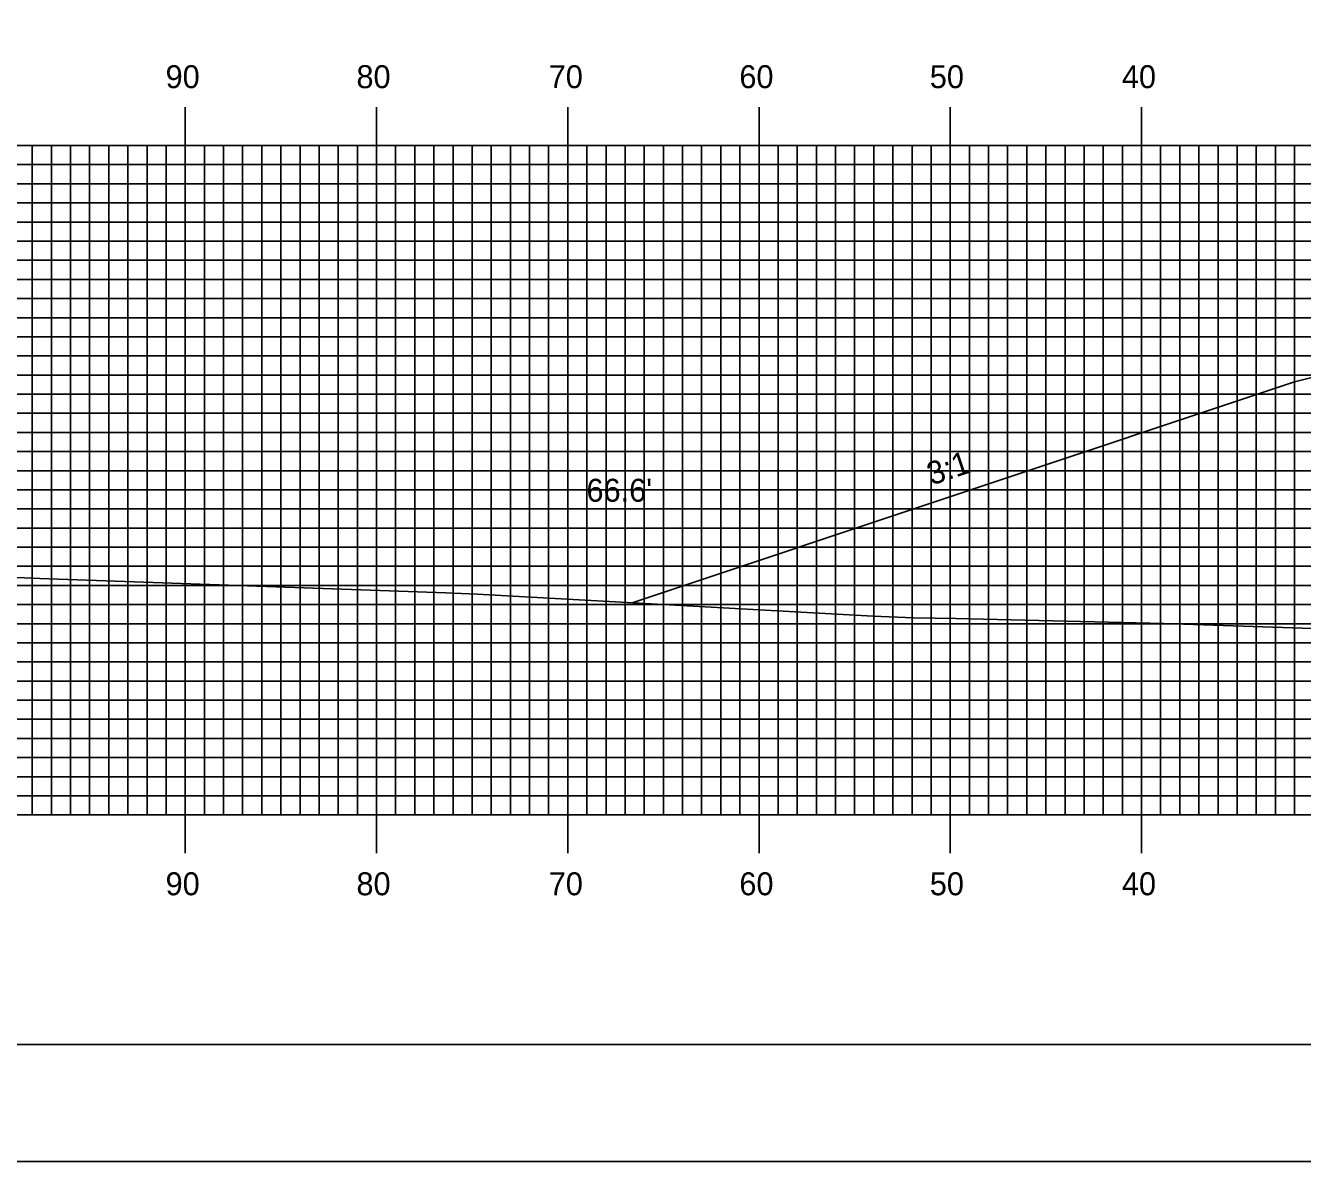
# Model space of a CAD drawing. Extents: x 1781467 to 1781810, y 442591 to 442811.
# Drawn here: x 1781534.1 to 1781600.8, y 442590.5 to 442649.9 of the extents above; entities that cross this region are included whole.
import ezdxf

# ---------------------------------------------------------------- set-up
doc = ezdxf.new("R2010")
doc.units = 0
for name, color, linetype in [('ANNOTATION', 7, 'Continuous'), ('BORDER', 7, 'Continuous'), ('D_Roadway_Centerline', 7, 'Continuous'), ('D_Roadway_SlopeLines', 7, 'Continuous'), ('D_Text_Standard', 7, 'Continuous'), ('H_V ANNOTATION', 7, 'Continuous'), ('MAJOR', 7, 'Continuous'), ('MINOR', 7, 'Continuous'), ('PLOT BOUNDARY', 7, 'Continuous'), ('S_Roadway_Centerline', 7, 'Continuous')]:
    doc.layers.add(name, color=color, linetype=linetype)

msp = doc.modelspace()

# ---------------------------------------------------------------- linework, layer by layer
at = {"layer": 'BORDER'}
msp.add_lwpolyline([(1781482.808, 442596.665), (1781802.808, 442596.665), (1781802.808, 442806.665), (1781482.808, 442806.665)], close=True, dxfattribs=at)
at = {"layer": 'D_Roadway_Centerline'}
msp.add_lwpolyline([(1781565.778, 442619.76), (1781600.408, 442631.303), (1781602.234, 442631.759), (1781612.408, 442634.303), (1781620.408, 442634.623), (1781632.408, 442634.863), (1781644.408, 442634.623), (1781652.408, 442634.303), (1781662.582, 442631.759), (1781664.408, 442631.303), (1781705.97, 442617.449)], dxfattribs=at)
at = {"layer": 'D_Roadway_SlopeLines'}
msp.add_lwpolyline([(1781612.408, 442634.303), (1781600.408, 442631.303), (1781565.778, 442619.76)], dxfattribs=at)
at = {"layer": 'MAJOR'}
for p, q in [((1781542.408, 442645.669), (1781542.408, 442643.665)), ((1781552.408, 442645.669), (1781552.408, 442643.665)), ((1781562.408, 442645.669), (1781562.408, 442643.665)), ((1781572.408, 442645.669), (1781572.408, 442643.665)), ((1781582.408, 442645.669), (1781582.408, 442643.665)), ((1781592.408, 442645.669), (1781592.408, 442643.665)), ((1781492.408, 442643.665), (1781772.408, 442643.665)), ((1781492.408, 442643.665), (1781772.408, 442643.665)), ((1781542.408, 442608.665), (1781542.408, 442643.665)), ((1781552.408, 442608.665), (1781552.408, 442643.665)), ((1781562.408, 442608.665), (1781562.408, 442643.665)), ((1781572.408, 442608.665), (1781572.408, 442643.665)), ((1781582.408, 442608.665), (1781582.408, 442643.665)), ((1781592.408, 442608.665), (1781592.408, 442643.665)), ((1781492.408, 442638.665), (1781772.408, 442638.665)), ((1781492.408, 442633.665), (1781772.408, 442633.665)), ((1781492.408, 442628.665), (1781772.408, 442628.665)), ((1781492.408, 442623.665), (1781772.408, 442623.665)), ((1781492.408, 442618.665), (1781772.408, 442618.665)), ((1781492.408, 442613.665), (1781772.408, 442613.665)), ((1781492.408, 442608.665), (1781772.408, 442608.665)), ((1781492.408, 442608.665), (1781772.408, 442608.665)), ((1781542.408, 442606.661), (1781542.408, 442608.665)), ((1781552.408, 442606.661), (1781552.408, 442608.665)), ((1781562.408, 442606.661), (1781562.408, 442608.665)), ((1781572.408, 442606.661), (1781572.408, 442608.665)), ((1781582.408, 442606.661), (1781582.408, 442608.665)), ((1781592.408, 442606.661), (1781592.408, 442608.665))]:
    msp.add_line(p, q, dxfattribs=at)
at = {"layer": 'MINOR'}
for p, q in [((1781534.408, 442608.665), (1781534.408, 442643.665)), ((1781535.408, 442608.665), (1781535.408, 442643.665)), ((1781536.408, 442608.665), (1781536.408, 442643.665)), ((1781537.408, 442608.665), (1781537.408, 442643.665)), ((1781538.408, 442608.665), (1781538.408, 442643.665)), ((1781539.408, 442608.665), (1781539.408, 442643.665)), ((1781540.408, 442608.665), (1781540.408, 442643.665)), ((1781541.408, 442608.665), (1781541.408, 442643.665)), ((1781543.408, 442608.665), (1781543.408, 442643.665)), ((1781544.408, 442608.665), (1781544.408, 442643.665)), ((1781545.408, 442608.665), (1781545.408, 442643.665)), ((1781546.408, 442608.665), (1781546.408, 442643.665)), ((1781547.408, 442608.665), (1781547.408, 442643.665)), ((1781548.408, 442608.665), (1781548.408, 442643.665)), ((1781549.408, 442608.665), (1781549.408, 442643.665)), ((1781550.408, 442608.665), (1781550.408, 442643.665)), ((1781551.408, 442608.665), (1781551.408, 442643.665)), ((1781553.408, 442608.665), (1781553.408, 442643.665)), ((1781554.408, 442608.665), (1781554.408, 442643.665)), ((1781555.408, 442608.665), (1781555.408, 442643.665)), ((1781556.408, 442608.665), (1781556.408, 442643.665)), ((1781557.408, 442608.665), (1781557.408, 442643.665)), ((1781558.408, 442608.665), (1781558.408, 442643.665)), ((1781559.408, 442608.665), (1781559.408, 442643.665)), ((1781560.408, 442608.665), (1781560.408, 442643.665)), ((1781561.408, 442608.665), (1781561.408, 442643.665)), ((1781563.408, 442608.665), (1781563.408, 442643.665)), ((1781564.408, 442608.665), (1781564.408, 442643.665)), ((1781565.408, 442608.665), (1781565.408, 442643.665)), ((1781566.408, 442608.665), (1781566.408, 442643.665)), ((1781567.408, 442608.665), (1781567.408, 442643.665)), ((1781568.408, 442608.665), (1781568.408, 442643.665)), ((1781569.408, 442608.665), (1781569.408, 442643.665)), ((1781570.408, 442608.665), (1781570.408, 442643.665)), ((1781571.408, 442608.665), (1781571.408, 442643.665)), ((1781573.408, 442608.665), (1781573.408, 442643.665)), ((1781574.408, 442608.665), (1781574.408, 442643.665)), ((1781575.408, 442608.665), (1781575.408, 442643.665)), ((1781576.408, 442608.665), (1781576.408, 442643.665)), ((1781577.408, 442608.665), (1781577.408, 442643.665)), ((1781578.408, 442608.665), (1781578.408, 442643.665)), ((1781579.408, 442608.665), (1781579.408, 442643.665)), ((1781580.408, 442608.665), (1781580.408, 442643.665)), ((1781581.408, 442608.665), (1781581.408, 442643.665)), ((1781583.408, 442608.665), (1781583.408, 442643.665)), ((1781584.408, 442608.665), (1781584.408, 442643.665)), ((1781585.408, 442608.665), (1781585.408, 442643.665)), ((1781586.408, 442608.665), (1781586.408, 442643.665)), ((1781587.408, 442608.665), (1781587.408, 442643.665)), ((1781588.408, 442608.665), (1781588.408, 442643.665)), ((1781589.408, 442608.665), (1781589.408, 442643.665)), ((1781590.408, 442608.665), (1781590.408, 442643.665)), ((1781591.408, 442608.665), (1781591.408, 442643.665)), ((1781593.408, 442608.665), (1781593.408, 442643.665)), ((1781594.408, 442608.665), (1781594.408, 442643.665)), ((1781595.408, 442608.665), (1781595.408, 442643.665)), ((1781596.408, 442608.665), (1781596.408, 442643.665)), ((1781597.408, 442608.665), (1781597.408, 442643.665)), ((1781598.408, 442608.665), (1781598.408, 442643.665)), ((1781599.408, 442608.665), (1781599.408, 442643.665)), ((1781600.408, 442608.665), (1781600.408, 442643.665)), ((1781492.408, 442642.665), (1781772.408, 442642.665)), ((1781492.408, 442641.665), (1781772.408, 442641.665)), ((1781492.408, 442640.665), (1781772.408, 442640.665)), ((1781492.408, 442639.665), (1781772.408, 442639.665)), ((1781492.408, 442637.665), (1781772.408, 442637.665)), ((1781492.408, 442636.665), (1781772.408, 442636.665)), ((1781492.408, 442635.665), (1781772.408, 442635.665)), ((1781492.408, 442634.665), (1781772.408, 442634.665)), ((1781492.408, 442632.665), (1781772.408, 442632.665)), ((1781492.408, 442631.665), (1781772.408, 442631.665)), ((1781492.408, 442630.665), (1781772.408, 442630.665)), ((1781492.408, 442629.665), (1781772.408, 442629.665)), ((1781492.408, 442627.665), (1781772.408, 442627.665)), ((1781492.408, 442626.665), (1781772.408, 442626.665)), ((1781492.408, 442625.665), (1781772.408, 442625.665)), ((1781492.408, 442624.665), (1781772.408, 442624.665)), ((1781492.408, 442622.665), (1781772.408, 442622.665)), ((1781492.408, 442621.665), (1781772.408, 442621.665)), ((1781492.408, 442620.665), (1781772.408, 442620.665)), ((1781492.408, 442619.665), (1781772.408, 442619.665)), ((1781492.408, 442617.665), (1781772.408, 442617.665)), ((1781492.408, 442616.665), (1781772.408, 442616.665)), ((1781492.408, 442615.665), (1781772.408, 442615.665)), ((1781492.408, 442614.665), (1781772.408, 442614.665)), ((1781492.408, 442612.665), (1781772.408, 442612.665)), ((1781492.408, 442611.665), (1781772.408, 442611.665)), ((1781492.408, 442610.665), (1781772.408, 442610.665)), ((1781492.408, 442609.665), (1781772.408, 442609.665))]:
    msp.add_line(p, q, dxfattribs=at)
at = {"layer": 'PLOT BOUNDARY'}
msp.add_lwpolyline([(1781466.621, 442590.547), (1781806.621, 442590.547), (1781806.621, 442810.547), (1781466.621, 442810.547)], close=True, dxfattribs=at)
at = {"layer": 'S_Roadway_Centerline'}
msp.add_lwpolyline([(1781492.408, 442622.895), (1781504.209, 442622.226), (1781519.145, 442621.714), (1781534.811, 442621.024), (1781535.76, 442621), (1781536.769, 442620.965), (1781556.039, 442620.281), (1781557.67, 442620.21), (1781578.382, 442619.059), (1781580.48, 442618.972), (1781582.705, 442618.928), (1781593.567, 442618.68), (1781608.597, 442618.177)], dxfattribs=at)

# ---------------------------------------------------------------- texts
at = {"layer": 'ANNOTATION'}
msp.add_text('3:1', height=1.2, rotation=18.43478, dxfattribs=at).set_placement((1781581.432, 442625.886))
at = {"layer": 'D_Text_Standard'}
msp.add_text("66.6'", height=1.2, dxfattribs=at).set_placement((1781563.386, 442625.042))
at = {"layer": 'H_V ANNOTATION'}
for s, p in [('90', (1781541.38, 442646.665)), ('80', (1781551.359, 442646.665)), ('70', (1781561.412, 442646.665)), ('60', (1781571.38, 442646.665)), ('50', (1781581.337, 442646.665)), ('40', (1781591.38, 442646.665)), ('90', (1781541.38, 442604.465)), ('80', (1781551.359, 442604.465)), ('70', (1781561.412, 442604.465)), ('60', (1781571.38, 442604.465)), ('50', (1781581.337, 442604.465)), ('40', (1781591.38, 442604.465))]:
    msp.add_text(s, height=1.2, dxfattribs=at).set_placement(p)

doc.saveas('drawing.dxf')
